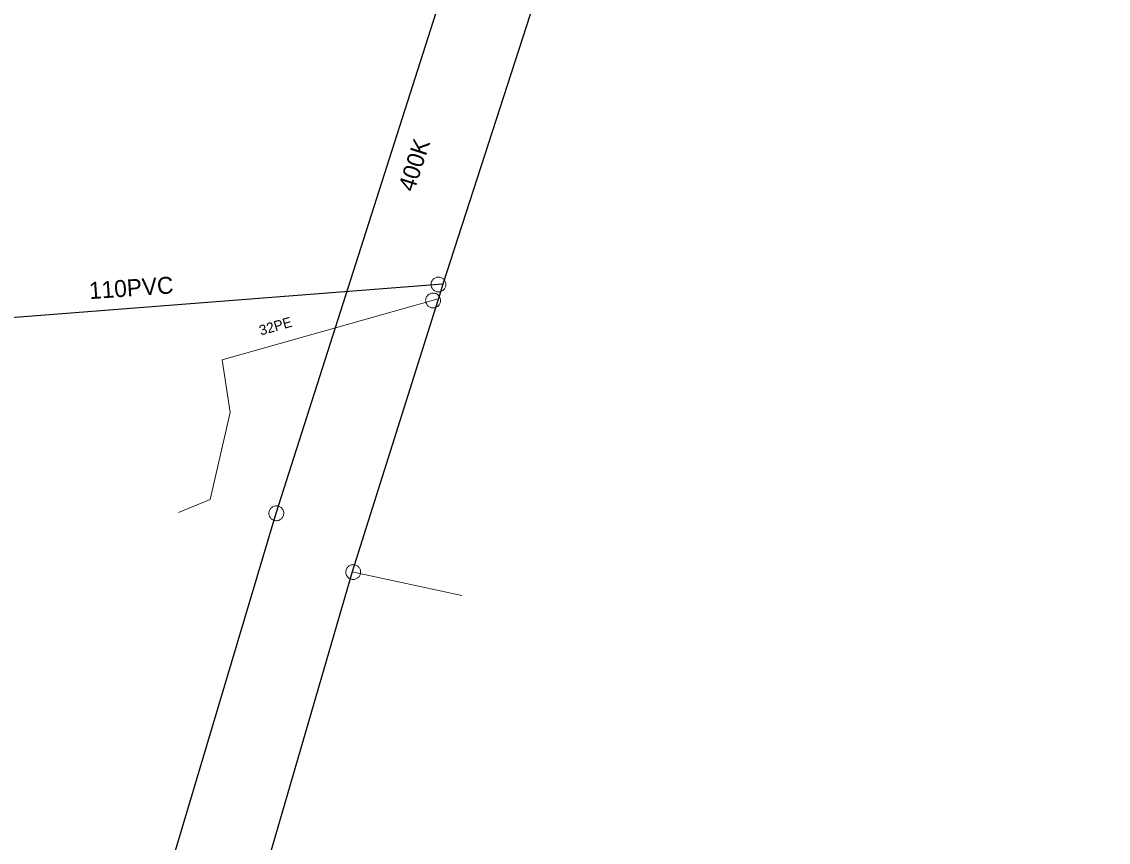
# Model space of a CAD drawing. Extents: x -741806 to -738704, y -1059275 to -1055387.
# Drawn here: x -740471.9 to -740407.9, y -1057417 to -1057368.6 of the extents above; entities that cross this region are included whole.
import ezdxf

# ---------------------------------------------------------------- set-up
doc = ezdxf.new("R2010")
doc.units = 0
doc.header["$LTSCALE"] = 0.4
for name, color, linetype, lineweight in [('2', 7, 'Continuous', 25), ('21', 7, 'Continuous', 13), ('3', 7, 'Continuous', 13), ('51', 7, 'Continuous', 13), ('52', 7, 'Continuous', 25)]:
    doc.layers.add(name, color=color, linetype=linetype, lineweight=lineweight)
for name, color, linetype in [('5', 7, 'Continuous'), ('53', 7, 'Continuous'), ('54', 7, 'Continuous')]:
    doc.layers.add(name, color=color, linetype=linetype)

msp = doc.modelspace()

# ---------------------------------------------------------------- linework, layer by layer
at = {"layer": '2'}
msp.add_lwpolyline([(-740463.206, -1057418.767), (-740456.879, -1057397.58), (-740443.219, -1057354.797), (-740443.287, -1057349.189), (-740432.452, -1057314.649), (-740420.603, -1057275.773), (-740415.289, -1057258.669)], dxfattribs=at)
at = {"layer": '21'}
for points in [[(-740447.335, -1057384.957), (-740460.079, -1057388.55), (-740459.6, -1057391.639), (-740460.77, -1057396.77), (-740462.649, -1057397.54)], [(-740452.412, -1057401.031), (-740452.329, -1057401.048), (-740445.939, -1057402.423)]]:
    msp.add_lwpolyline(points, dxfattribs=at)
at = {"layer": '3'}
msp.add_lwpolyline([(-740456.753, -1057397.16), (-740456.797, -1057397.15), (-740456.842, -1057397.144), (-740456.888, -1057397.142), (-740456.933, -1057397.146), (-740456.978, -1057397.154), (-740457.023, -1057397.167), (-740457.065, -1057397.185), (-740457.106, -1057397.206), (-740457.143, -1057397.232), (-740457.178, -1057397.262), (-740457.209, -1057397.295), (-740457.238, -1057397.331), (-740457.261, -1057397.37), (-740457.282, -1057397.411), (-740457.297, -1057397.455), (-740457.308, -1057397.499), (-740457.313, -1057397.545), (-740457.315, -1057397.59), (-740457.311, -1057397.636), (-740457.303, -1057397.681), (-740457.29, -1057397.725), (-740457.273, -1057397.766), (-740457.251, -1057397.807), (-740457.226, -1057397.845), (-740457.195, -1057397.88), (-740457.162, -1057397.911), (-740457.126, -1057397.94), (-740457.087, -1057397.964), (-740457.046, -1057397.984), (-740457.002, -1057397.999), (-740456.958, -1057398.01), (-740456.913, -1057398.016), (-740456.867, -1057398.017), (-740456.821, -1057398.013), (-740456.777, -1057398.005), (-740456.732, -1057397.993), (-740456.69, -1057397.975), (-740456.649, -1057397.953), (-740456.612, -1057397.927), (-740456.578, -1057397.898), (-740456.546, -1057397.865), (-740456.517, -1057397.828), (-740456.493, -1057397.79), (-740456.473, -1057397.748), (-740456.458, -1057397.705), (-740456.447, -1057397.66), (-740456.441, -1057397.615), (-740456.44, -1057397.57), (-740456.444, -1057397.524), (-740456.452, -1057397.478), (-740456.465, -1057397.435), (-740456.482, -1057397.392), (-740456.504, -1057397.352), (-740456.53, -1057397.314), (-740456.56, -1057397.279), (-740456.593, -1057397.247), (-740456.629, -1057397.22), (-740456.668, -1057397.196), (-740456.709, -1057397.176), (-740456.752, -1057397.16)], dxfattribs=at)
at = {"layer": '51'}
for points in [[(-740446.889, -1057384.101), (-740446.891, -1057384.056), (-740446.898, -1057384.011), (-740446.91, -1057383.966), (-740446.926, -1057383.924), (-740446.947, -1057383.883), (-740446.972, -1057383.844), (-740447.001, -1057383.809), (-740447.033, -1057383.776), (-740447.069, -1057383.748), (-740447.107, -1057383.723), (-740447.148, -1057383.702), (-740447.191, -1057383.685), (-740447.235, -1057383.673), (-740447.28, -1057383.666), (-740447.326, -1057383.664), (-740447.372, -1057383.666), (-740447.417, -1057383.673), (-740447.461, -1057383.685), (-740447.504, -1057383.702), (-740447.545, -1057383.723), (-740447.583, -1057383.748), (-740447.619, -1057383.776), (-740447.651, -1057383.809), (-740447.68, -1057383.844), (-740447.705, -1057383.883), (-740447.726, -1057383.924), (-740447.742, -1057383.966), (-740447.754, -1057384.011), (-740447.761, -1057384.056), (-740447.764, -1057384.102), (-740447.761, -1057384.147), (-740447.754, -1057384.192), (-740447.742, -1057384.237), (-740447.726, -1057384.279), (-740447.705, -1057384.32), (-740447.68, -1057384.359), (-740447.651, -1057384.394), (-740447.619, -1057384.427), (-740447.583, -1057384.455), (-740447.545, -1057384.48), (-740447.504, -1057384.501), (-740447.461, -1057384.518), (-740447.417, -1057384.529), (-740447.372, -1057384.537), (-740447.326, -1057384.539), (-740447.28, -1057384.537), (-740447.235, -1057384.529), (-740447.191, -1057384.518), (-740447.148, -1057384.501), (-740447.107, -1057384.48), (-740447.069, -1057384.455), (-740447.033, -1057384.427), (-740447.001, -1057384.394), (-740446.972, -1057384.359), (-740446.947, -1057384.32), (-740446.926, -1057384.279), (-740446.91, -1057384.237), (-740446.898, -1057384.192), (-740446.891, -1057384.147), (-740446.889, -1057384.102)], [(-740447.774, -1057385.46), (-740447.73, -1057385.472), (-740447.685, -1057385.479), (-740447.639, -1057385.481), (-740447.594, -1057385.478), (-740447.548, -1057385.47), (-740447.504, -1057385.458), (-740447.461, -1057385.441), (-740447.42, -1057385.421), (-740447.383, -1057385.395), (-740447.347, -1057385.366), (-740447.315, -1057385.333), (-740447.286, -1057385.297), (-740447.261, -1057385.259), (-740447.241, -1057385.218), (-740447.225, -1057385.175), (-740447.213, -1057385.13), (-740447.206, -1057385.085), (-740447.205, -1057385.04), (-740447.208, -1057384.994), (-740447.216, -1057384.948), (-740447.228, -1057384.905), (-740447.244, -1057384.862), (-740447.266, -1057384.821), (-740447.29, -1057384.783), (-740447.32, -1057384.748), (-740447.353, -1057384.715), (-740447.388, -1057384.687), (-740447.427, -1057384.662), (-740447.468, -1057384.642), (-740447.511, -1057384.625), (-740447.555, -1057384.615), (-740447.6, -1057384.608), (-740447.646, -1057384.606), (-740447.691, -1057384.608), (-740447.737, -1057384.616), (-740447.781, -1057384.628), (-740447.823, -1057384.645), (-740447.865, -1057384.666), (-740447.902, -1057384.692), (-740447.937, -1057384.72), (-740447.97, -1057384.753), (-740447.999, -1057384.789), (-740448.023, -1057384.828), (-740448.044, -1057384.868), (-740448.06, -1057384.911), (-740448.072, -1057384.956), (-740448.078, -1057385.001), (-740448.08, -1057385.046), (-740448.077, -1057385.093), (-740448.069, -1057385.138), (-740448.057, -1057385.182), (-740448.041, -1057385.225), (-740448.019, -1057385.265), (-740447.995, -1057385.303), (-740447.965, -1057385.339), (-740447.932, -1057385.371), (-740447.897, -1057385.399), (-740447.858, -1057385.424), (-740447.817, -1057385.444), (-740447.775, -1057385.46)]]:
    msp.add_lwpolyline(points, dxfattribs=at)
msp.add_lwpolyline([(-740452.759, -1057400.891), (-740452.773, -1057400.934), (-740452.782, -1057400.979), (-740452.786, -1057401.025), (-740452.786, -1057401.07), (-740452.78, -1057401.116), (-740452.77, -1057401.161), (-740452.755, -1057401.204), (-740452.737, -1057401.246), (-740452.713, -1057401.285), (-740452.686, -1057401.322), (-740452.655, -1057401.356), (-740452.62, -1057401.386), (-740452.583, -1057401.413), (-740452.543, -1057401.435), (-740452.501, -1057401.453), (-740452.457, -1057401.467), (-740452.412, -1057401.476), (-740452.367, -1057401.48), (-740452.321, -1057401.479), (-740452.275, -1057401.474), (-740452.231, -1057401.463), (-740452.187, -1057401.449), (-740452.146, -1057401.43), (-740452.106, -1057401.407), (-740452.069, -1057401.379), (-740452.036, -1057401.348), (-740452.006, -1057401.314), (-740451.979, -1057401.276), (-740451.957, -1057401.236), (-740451.938, -1057401.194), (-740451.925, -1057401.151), (-740451.916, -1057401.106), (-740451.912, -1057401.06), (-740451.912, -1057401.015), (-740451.918, -1057400.969), (-740451.928, -1057400.924), (-740451.943, -1057400.881), (-740451.961, -1057400.839), (-740451.986, -1057400.8), (-740452.012, -1057400.764), (-740452.044, -1057400.73), (-740452.078, -1057400.699), (-740452.116, -1057400.673), (-740452.155, -1057400.65), (-740452.197, -1057400.632), (-740452.241, -1057400.618), (-740452.286, -1057400.61), (-740452.331, -1057400.605), (-740452.378, -1057400.606), (-740452.423, -1057400.612), (-740452.468, -1057400.622), (-740452.511, -1057400.636), (-740452.553, -1057400.656), (-740452.592, -1057400.678), (-740452.629, -1057400.706), (-740452.663, -1057400.737), (-740452.692, -1057400.771), (-740452.719, -1057400.809), (-740452.741, -1057400.849)], close=True, dxfattribs=at)
at = {"layer": '52'}
for points in [[(-740407.857, -1057263.098), (-740439.467, -1057360.607), (-740447.059, -1057384.081), (-740447.248, -1057384.679), (-740452.412, -1057401.031), (-740457.603, -1057418.83), (-740467.015, -1057450.047), (-740468.397, -1057454.838), (-740469.89, -1057459.936), (-740472.616, -1057468.997), (-740478.407, -1057487.088), (-740480.659, -1057495.081), (-740486.488, -1057512.648), (-740486.78, -1057514.456), (-740493.754, -1057537.497), (-740495.864, -1057543.049), (-740500.778, -1057560.762), (-740501.975, -1057565.431)], [(-740447.059, -1057384.081), (-740482.611, -1057386.857), (-740514.765, -1057392.747), (-740521.043, -1057394.158), (-740540.033, -1057397.307), (-740548.526, -1057398.619), (-740563.186, -1057401.392), (-740569.092, -1057402.71), (-740590.765, -1057406.389), (-740595.761, -1057407.486), (-740608.386, -1057409.341), (-740629.568, -1057413.446)]]:
    msp.add_lwpolyline(points, dxfattribs=at)

# ---------------------------------------------------------------- texts
at = {"layer": '5'}
msp.add_text('400K', height=1, rotation=72, dxfattribs=at).set_placement((-740448.765, -1057378.697))
at = {"layer": '53'}
msp.add_text('110PVC', height=1, rotation=4, dxfattribs=at).set_placement((-740467.882, -1057384.969))
at = {"layer": '54'}
msp.add_text('32PE', height=0.6, rotation=16, dxfattribs=at).set_placement((-740457.787, -1057387.113))

doc.saveas('drawing.dxf')
